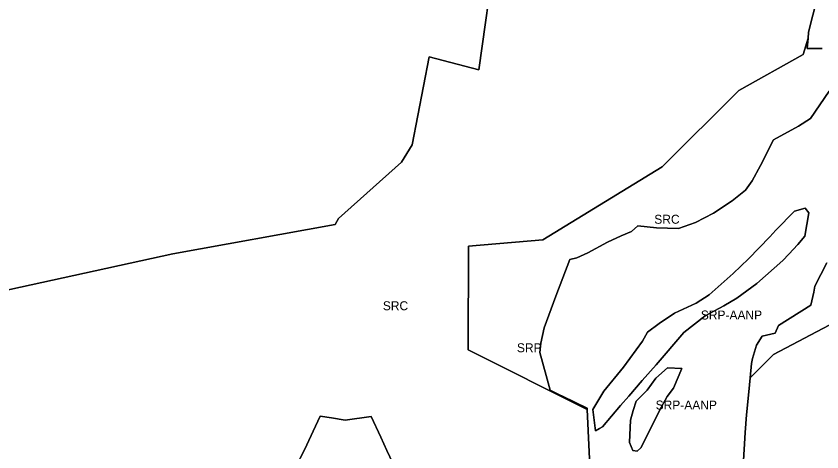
# Model space of a CAD drawing. Extents: x 598968 to 613553, y 4409678 to 4430833.
# Drawn here: x 600257 to 601335, y 4413340 to 4413923 of the extents above; entities that cross this region are included whole.
import ezdxf

# ---------------------------------------------------------------- set-up
doc = ezdxf.new("R2010")
doc.units = 0
for name, color, linetype in [('Sòl Rústic Comú', 7, 'Continuous'), ('Sòl Rústic Protegit', 7, 'Continuous'), ('Sòl Rústic Protegit - Alt Nivell de Protecció', 7, 'Continuous')]:
    doc.layers.add(name, color=color, linetype=linetype)

msp = doc.modelspace()

# ---------------------------------------------------------------- linework, layer by layer
at = {"layer": 'Sòl Rústic Comú'}
for points in [[(600897.9897, 4414007.1854), (600876.0515, 4413851.1852), (600809.9259, 4413868.6852), (600786.9251, 4413750.685), (600772.5499, 4413727.685), (600688.2987, 4413652.1848), (600683.9237, 4413644.1848), (600466.5463, 4413604.6844), (600158.2303, 4413537.684)], [(600158.2303, 4413537.684), (600466.5463, 4413604.6844), (600683.9237, 4413644.1848), (600688.2987, 4413652.1848), (600772.5499, 4413727.685), (600786.9251, 4413750.685), (600809.9259, 4413868.6852), (600876.0515, 4413851.1852), (600897.9897, 4414007.1854)], [(601026.0509, 4413292.685), (601021.1763, 4413396.685), (600861.7373, 4413476.1848), (600862.4255, 4413615.185), (600961.6765, 4413623.6852), (601121.6785, 4413721.1854), (601224.3675, 4413823.6856), (601310.3061, 4413871.6858), (601316.8687, 4413893.6858), (601317.6187, 4413901.1858), (601321.6189, 4413917.686), (601327.3065, 4413939.686)], [(601335.9313, 4413879.6858), (601315.4937, 4413879.6858), (601316.8687, 4413893.6858), (601310.3061, 4413871.6858), (601224.3675, 4413823.6856), (601121.6785, 4413721.1854), (600961.6765, 4413623.6852), (600862.4255, 4413615.185), (600861.7373, 4413476.1848), (601021.1763, 4413396.685), (601021.1137, 4413398.185), (600988.3483, 4413414.263), (600987.4885, 4413414.685), (600986.8459, 4413414.9886), (600971.6133, 4413422.185), (600966.2383, 4413442.185), (600957.7383, 4413472.685), (600959.3635, 4413485.185), (600963.8635, 4413505.685), (600979.1139, 4413548.185), (600997.9267, 4413597.1852), (601007.5519, 4413599.6852), (601021.9895, 4413606.1852), (601048.2399, 4413620.6852), (601066.6151, 4413629.1852), (601080.6777, 4413634.6854), (601089.0529, 4413642.1854), (601113.9907, 4413639.6854), (601143.3659, 4413638.6854), (601166.0537, 4413646.6854), (601190.2415, 4413659.1854), (601215.0543, 4413675.6856), (601233.2421, 4413690.1856), (601242.1797, 4413702.6856), (601253.0549, 4413723.1856), (601270.7427, 4413757.6856), (601304.2431, 4413775.6858), (601320.2433, 4413786.1858), (601345.1813, 4413822.6858)], [(601353.3677, 4413513.6856), (601270.6791, 4413470.1854), (601239.4291, 4413438.9356), (601239.1787, 4413438.6854), (601237.3661, 4413420.1854), (601234.4909, 4413389.1854), (601232.5533, 4413365.6852), (601230.0531, 4413320.6852)], [(600630.7343, 4413319.1844), (600642.8597, 4413342.6844), (600657.7973, 4413374.1844), (600663.7975, 4413387.6846), (600678.8601, 4413385.1846), (600678.9789, 4413385.1654), (600679.1685, 4413385.1348), (600697.4229, 4413382.1846), (600732.1107, 4413387.1846), (600745.0483, 4413359.6846), (600753.1107, 4413341.6846), (600761.1107, 4413324.6846)]]:
    msp.add_lwpolyline(points, dxfattribs=at)
at = {"layer": 'Sòl Rústic Protegit'}
for points in [[(601327.3065, 4413939.686), (601321.6189, 4413917.686), (601317.6187, 4413901.1858), (601316.8687, 4413893.6858), (601315.4937, 4413879.6858), (601335.9313, 4413879.6858)], [(601345.1813, 4413822.6858), (601320.2433, 4413786.1858), (601304.2431, 4413775.6858), (601270.7427, 4413757.6856), (601253.0549, 4413723.1856), (601242.1797, 4413702.6856), (601233.2421, 4413690.1856), (601215.0543, 4413675.6856), (601190.2415, 4413659.1854), (601166.0537, 4413646.6854), (601143.3659, 4413638.6854), (601113.9907, 4413639.6854), (601089.0529, 4413642.1854), (601080.6777, 4413634.6854), (601066.6151, 4413629.1852), (601048.2399, 4413620.6852), (601021.9895, 4413606.1852), (601007.5519, 4413599.6852), (600997.9267, 4413597.1852), (600979.1139, 4413548.185), (600963.8635, 4413505.685), (600959.3635, 4413485.185), (600957.7383, 4413472.685), (600966.2383, 4413442.185), (600971.6133, 4413422.185), (600986.8459, 4413414.9886), (600987.4885, 4413414.685), (600988.3483, 4413414.263), (601021.1137, 4413398.185), (601021.1763, 4413396.685), (601026.0509, 4413292.685)], [(601230.0531, 4413320.6852), (601232.5533, 4413365.6852), (601234.4909, 4413389.1854), (601237.3661, 4413420.1854), (601239.1787, 4413438.6854), (601241.1163, 4413458.1854), (601242.6789, 4413464.6854), (601247.9289, 4413482.6854), (601255.5541, 4413494.6854), (601272.7417, 4413498.6854), (601277.1793, 4413509.1854), (601320.6799, 4413536.1856), (601324.4301, 4413553.6856), (601326.1175, 4413561.6856), (601342.1803, 4413592.6856)], [(601342.1803, 4413592.6856), (601326.1175, 4413561.6856), (601324.4301, 4413553.6856), (601320.6799, 4413536.1856), (601277.1793, 4413509.1854), (601272.7417, 4413498.6854), (601255.5541, 4413494.6854), (601247.9289, 4413482.6854), (601242.6789, 4413464.6854), (601241.1163, 4413458.1854), (601239.1787, 4413438.6854), (601239.4291, 4413438.9356), (601270.6791, 4413470.1854), (601353.3677, 4413513.6856)], [(600761.1107, 4413324.6846), (600753.1107, 4413341.6846), (600745.0483, 4413359.6846), (600732.1107, 4413387.1846), (600697.4229, 4413382.1846), (600679.1685, 4413385.1348), (600678.9789, 4413385.1654), (600678.8601, 4413385.1846), (600663.7975, 4413387.6846), (600657.7973, 4413374.1844), (600642.8597, 4413342.6844), (600630.7343, 4413319.1844)]]:
    msp.add_lwpolyline(points, dxfattribs=at)
for points in [[(601037.6801, 4413371.0098), (601032.5551, 4413368.0098), (601029.4301, 4413393.0098), (601028.9301, 4413396.5098), (601043.3677, 4413421.0098), (601069.6801, 4413453.0098), (601095.2427, 4413488.0098), (601101.8051, 4413500.0098), (601117.3677, 4413511.5098), (601137.9301, 4413525.5098), (601166.8677, 4413539.0098), (601184.3677, 4413550.0098), (601216.5551, 4413578.5098), (601236.9301, 4413598.0098), (601265.8677, 4413627.5098), (601273.8677, 4413636.5098), (601298.4927, 4413662.0098), (601312.9927, 4413666.0098), (601317.7427, 4413660.0098), (601312.4927, 4413628.5098), (601303.3051, 4413617.5098), (601290.9927, 4413604.5098), (601283.0551, 4413596.0098), (601248.3677, 4413565.0098), (601221.6177, 4413545.5098), (601204.0551, 4413535.5098), (601178.9927, 4413522.0098), (601150.4301, 4413499.5098), (601113.6801, 4413456.5098), (601094.6177, 4413435.5098), (601076.8677, 4413414.5098), (601065.8051, 4413402.0098), (601041.9301, 4413373.5098)], [(601092.8677, 4413345.0098), (601087.9301, 4413340.5098), (601082.1801, 4413341.5098), (601077.9301, 4413352.5098), (601079.3677, 4413382.0098), (601082.6801, 4413395.0098), (601086.7427, 4413407.5098), (601101.4927, 4413422.5098), (601113.0551, 4413438.5098), (601128.5551, 4413452.5098), (601147.7427, 4413451.5098), (601136.6177, 4413425.0098), (601128.0551, 4413414.0098), (601117.8677, 4413395.0098), (601100.0551, 4413359.0098)]]:
    msp.add_lwpolyline(points, close=True, dxfattribs=at)
at = {"layer": 'Sòl Rústic Protegit - Alt Nivell de Protecció'}
for points in [[(601037.6801, 4413371.0098), (601041.9301, 4413373.5098), (601065.8051, 4413402.0098), (601076.8677, 4413414.5098), (601094.6177, 4413435.5098), (601113.6801, 4413456.5098), (601150.4301, 4413499.5098), (601178.9927, 4413522.0098), (601204.0551, 4413535.5098), (601221.6177, 4413545.5098), (601248.3677, 4413565.0098), (601283.0551, 4413596.0098), (601290.9927, 4413604.5098), (601303.3051, 4413617.5098), (601312.4927, 4413628.5098), (601317.7427, 4413660.0098), (601312.9927, 4413666.0098), (601298.4927, 4413662.0098), (601273.8677, 4413636.5098), (601265.8677, 4413627.5098), (601236.9301, 4413598.0098), (601216.5551, 4413578.5098), (601184.3677, 4413550.0098), (601166.8677, 4413539.0098), (601137.9301, 4413525.5098), (601117.3677, 4413511.5098), (601101.8051, 4413500.0098), (601095.2427, 4413488.0098), (601069.6801, 4413453.0098), (601043.3677, 4413421.0098), (601028.9301, 4413396.5098), (601029.4301, 4413393.0098), (601032.5551, 4413368.0098)], [(601092.8677, 4413345.0098), (601100.0551, 4413359.0098), (601117.8677, 4413395.0098), (601128.0551, 4413414.0098), (601136.6177, 4413425.0098), (601147.7427, 4413451.5098), (601128.5551, 4413452.5098), (601113.0551, 4413438.5098), (601101.4927, 4413422.5098), (601086.7427, 4413407.5098), (601082.6801, 4413395.0098), (601079.3677, 4413382.0098), (601077.9301, 4413352.5098), (601082.1801, 4413341.5098), (601087.9301, 4413340.5098)]]:
    msp.add_lwpolyline(points, close=True, dxfattribs=at)

# ---------------------------------------------------------------- texts
at = {"layer": 'Sòl Rústic Comú'}
for p in [(601111.0219, 4413645.1854), (600747.7529, 4413529.3932)]:
    msp.add_text('SRC', height=12, dxfattribs=at).set_placement(p)
at = {"layer": 'Sòl Rústic Protegit'}
msp.add_text('SRP', height=12, dxfattribs=at).set_placement((600927.1987, 4413473.1591))
at = {"layer": 'Sòl Rústic Protegit - Alt Nivell de Protecció'}
for p in [(601173.3364, 4413517.0098), (601112.8364, 4413396.5098)]:
    msp.add_text('SRP-AANP', height=12, dxfattribs=at).set_placement(p)

doc.saveas('drawing.dxf')
